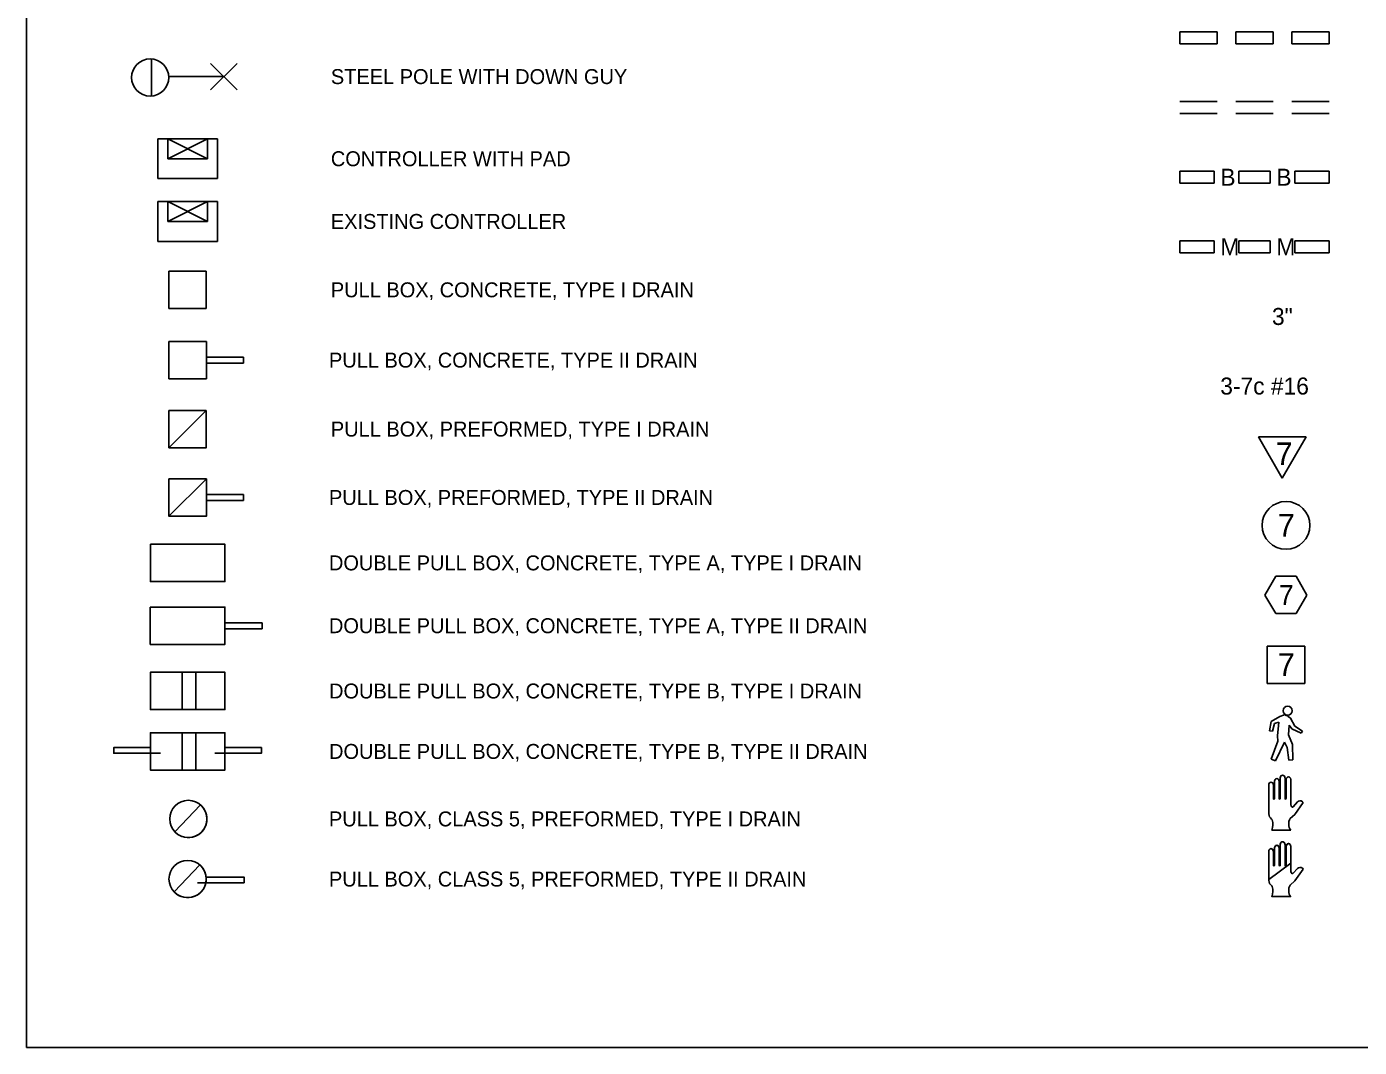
# Model space of a CAD drawing. Extents: x -439.1 to -407.9, y -458.1 to -437.7.
# Drawn here: x -439.11 to -425.73, y -458.05 to -447.8 of the extents above; entities that cross this region are included whole.
import ezdxf

# ---------------------------------------------------------------- set-up
doc = ezdxf.new("R2010")
doc.units = 0
for name, color, linetype in [('Draft_Named_Boundary', 7, 'Continuous'), ('Level 4', 7, 'Continuous'), ('Lighting_Signals-Conduit', 7, 'Continuous'), ('Lighting_Signals-Equipment', 7, 'Continuous')]:
    doc.layers.add(name, color=color, linetype=linetype)

msp = doc.modelspace()

# ---------------------------------------------------------------- linework, layer by layer
at = {"layer": 'Draft_Named_Boundary'}
msp.add_lwpolyline([(-439.109, -458.051), (-407.859, -458.051), (-407.859, -437.676), (-439.109, -437.676)], close=True, dxfattribs=at)
at = {"layer": 'Level 4'}
for p, q in [((-427.533, -447.85), (-427.533, -447.97)), ((-427.533, -447.85), (-427.157, -447.85)), ((-427.157, -447.85), (-427.157, -447.97)), ((-426.97, -447.85), (-426.97, -447.97)), ((-426.97, -447.85), (-426.595, -447.85)), ((-426.595, -447.85), (-426.595, -447.97)), ((-426.408, -447.85), (-426.408, -447.97)), ((-426.408, -447.85), (-426.033, -447.85)), ((-426.033, -447.85), (-426.033, -447.97)), ((-427.533, -447.97), (-427.157, -447.97)), ((-426.97, -447.97), (-426.595, -447.97)), ((-426.408, -447.97), (-426.033, -447.97)), ((-437.856, -448.121), (-437.856, -448.495)), ((-436.997, -448.167), (-437.262, -448.432)), ((-437.262, -448.167), (-436.997, -448.432)), ((-437.682, -448.299), (-437.13, -448.299)), ((-427.533, -448.549), (-427.157, -448.549)), ((-426.97, -448.549), (-426.595, -448.549)), ((-426.408, -448.549), (-426.033, -448.549)), ((-427.533, -448.669), (-427.157, -448.669)), ((-426.97, -448.669), (-426.595, -448.669)), ((-426.408, -448.669), (-426.033, -448.669)), ((-427.533, -449.369), (-427.533, -449.25)), ((-427.533, -449.25), (-427.188, -449.25)), ((-427.188, -449.25), (-427.188, -449.369)), ((-426.94, -449.369), (-426.94, -449.25)), ((-426.94, -449.25), (-426.625, -449.25)), ((-426.625, -449.25), (-426.625, -449.369)), ((-426.378, -449.369), (-426.378, -449.25)), ((-426.378, -449.25), (-426.033, -449.25)), ((-426.033, -449.25), (-426.033, -449.369)), ((-427.188, -449.369), (-427.533, -449.369)), ((-426.625, -449.369), (-426.94, -449.369)), ((-426.033, -449.369), (-426.378, -449.369)), ((-427.533, -450.068), (-427.533, -449.949)), ((-427.533, -449.949), (-427.188, -449.949)), ((-427.188, -450.068), (-427.533, -450.068)), ((-427.188, -449.949), (-427.188, -450.068)), ((-426.94, -450.068), (-426.94, -449.949)), ((-426.94, -449.949), (-426.625, -449.949)), ((-426.625, -450.068), (-426.94, -450.068)), ((-426.625, -449.949), (-426.625, -450.068)), ((-426.378, -450.068), (-426.378, -449.949)), ((-426.378, -449.949), (-426.033, -449.949)), ((-426.033, -450.068), (-426.378, -450.068)), ((-426.033, -449.949), (-426.033, -450.068)), ((-437.306, -450.254), (-437.68, -450.254)), ((-437.68, -450.254), (-437.68, -450.629)), ((-437.306, -450.629), (-437.306, -450.254)), ((-437.68, -450.629), (-437.306, -450.629)), ((-437.305, -450.96), (-437.68, -450.96)), ((-437.68, -450.96), (-437.68, -451.335)), ((-437.305, -451.335), (-437.305, -450.96)), ((-437.305, -451.117), (-436.931, -451.117)), ((-436.931, -451.177), (-436.931, -451.117)), ((-437.305, -451.177), (-436.931, -451.177)), ((-437.68, -451.335), (-437.305, -451.335)), ((-437.68, -451.653), (-437.68, -452.028)), ((-437.68, -451.653), (-437.306, -451.653)), ((-437.306, -451.653), (-437.68, -452.028)), ((-437.306, -451.653), (-437.306, -452.028)), ((-426.264, -451.919), (-426.743, -451.919)), ((-426.743, -451.919), (-426.504, -452.333)), ((-426.504, -452.333), (-426.264, -451.919)), ((-437.68, -452.028), (-437.306, -452.028)), ((-437.68, -452.34), (-437.68, -452.715)), ((-437.68, -452.34), (-437.305, -452.34)), ((-437.68, -452.715), (-437.305, -452.34)), ((-437.305, -452.34), (-437.305, -452.715)), ((-437.305, -452.497), (-436.931, -452.497)), ((-437.305, -452.557), (-436.931, -452.557)), ((-436.931, -452.557), (-436.931, -452.497)), ((-437.68, -452.715), (-437.305, -452.715)), ((-426.677, -453.507), (-426.569, -453.319)), ((-426.569, -453.319), (-426.364, -453.319)), ((-426.256, -453.507), (-426.364, -453.319)), ((-426.677, -453.507), (-426.569, -453.694)), ((-426.256, -453.507), (-426.364, -453.694)), ((-437.118, -453.786), (-436.744, -453.786)), ((-436.744, -453.845), (-436.744, -453.786)), ((-426.569, -453.694), (-426.364, -453.694)), ((-437.118, -453.845), (-436.744, -453.845)), ((-426.654, -454.019), (-426.278, -454.019)), ((-426.654, -454.394), (-426.654, -454.019)), ((-426.278, -454.394), (-426.278, -454.019)), ((-437.867, -454.283), (-437.119, -454.283)), ((-426.654, -454.394), (-426.278, -454.394)), ((-437.119, -454.658), (-437.867, -454.658)), ((-426.614, -454.776), (-426.527, -454.726)), ((-426.527, -454.726), (-426.491, -454.714)), ((-426.491, -454.714), (-426.483, -454.707)), ((-426.491, -454.714), (-426.491, -454.714)), ((-426.483, -454.707), (-426.466, -454.716)), ((-426.466, -454.716), (-426.452, -454.717)), ((-426.452, -454.717), (-426.445, -454.728)), ((-426.445, -454.728), (-426.422, -454.745)), ((-426.422, -454.745), (-426.376, -454.825)), ((-437.867, -454.89), (-437.119, -454.89)), ((-426.632, -454.872), (-426.614, -454.776)), ((-426.602, -454.875), (-426.632, -454.872)), ((-426.58, -454.796), (-426.602, -454.875)), ((-426.537, -454.785), (-426.58, -454.796)), ((-426.551, -454.923), (-426.537, -454.785)), ((-426.433, -454.813), (-426.441, -454.912)), ((-426.406, -454.852), (-426.433, -454.813)), ((-426.315, -454.894), (-426.406, -454.852)), ((-426.376, -454.825), (-426.3, -454.876)), ((-426.3, -454.876), (-426.315, -454.894)), ((-426.614, -455.157), (-426.547, -454.976)), ((-426.481, -454.986), (-426.573, -455.173)), ((-426.547, -454.976), (-426.551, -454.923)), ((-426.453, -455.039), (-426.481, -454.986)), ((-426.441, -454.912), (-426.401, -455.01)), ((-426.401, -455.01), (-426.397, -455.163)), ((-426.573, -455.173), (-426.614, -455.157)), ((-426.438, -455.166), (-426.453, -455.039)), ((-426.397, -455.163), (-426.438, -455.166)), ((-437.119, -455.266), (-437.867, -455.266)), ((-426.639, -455.705), (-426.639, -455.413)), ((-426.592, -455.413), (-426.592, -455.551)), ((-426.581, -455.551), (-426.581, -455.378)), ((-426.534, -455.378), (-426.534, -455.551)), ((-426.523, -455.551), (-426.523, -455.343)), ((-426.476, -455.343), (-426.476, -455.551)), ((-426.465, -455.551), (-426.465, -455.361)), ((-426.418, -455.361), (-426.418, -455.602)), ((-437.365, -455.614), (-437.621, -455.886)), ((-437.365, -455.614), (-437.621, -455.886)), ((-426.413, -455.626), (-426.412, -455.63)), ((-426.393, -455.633), (-426.351, -455.586)), ((-426.301, -455.583), (-426.293, -455.591)), ((-426.418, -455.868), (-426.609, -455.868)), ((-426.639, -456.374), (-426.639, -456.081)), ((-426.592, -456.081), (-426.592, -456.22)), ((-426.581, -456.22), (-426.581, -456.047)), ((-426.534, -456.047), (-426.534, -456.22)), ((-426.523, -456.22), (-426.523, -456.012)), ((-426.476, -456.012), (-426.476, -456.22)), ((-426.465, -456.22), (-426.465, -456.029)), ((-426.418, -456.029), (-426.418, -456.201)), ((-437.372, -456.217), (-437.628, -456.49)), ((-437.372, -456.217), (-437.628, -456.49)), ((-426.639, -456.363), (-426.418, -456.201)), ((-426.418, -456.201), (-426.418, -456.271)), ((-426.413, -456.295), (-426.412, -456.298)), ((-426.393, -456.302), (-426.351, -456.254)), ((-426.301, -456.252), (-426.293, -456.26)), ((-426.418, -456.537), (-426.609, -456.537))]:
    msp.add_line(p, q, dxfattribs=at)
for points in [[(-437.306, -451.653), (-437.68, -452.028), (-437.306, -452.028)], [(-437.305, -452.34), (-437.68, -452.715), (-437.305, -452.715)], [(-437.867, -452.996), (-437.119, -452.996), (-437.119, -453.371), (-437.867, -453.371)], [(-437.868, -453.628), (-437.118, -453.628), (-437.118, -454.003), (-437.868, -454.003)], [(-426.639, -456.363), (-426.639, -456.081), (-426.634, -456.065), (-426.624, -456.057), (-426.61, -456.057), (-426.6, -456.062), (-426.592, -456.081), (-426.592, -456.22), (-426.589, -456.225), (-426.585, -456.225), (-426.582, -456.225), (-426.582, -456.22), (-426.581, -456.22), (-426.581, -456.047), (-426.581, -456.047), (-426.574, -456.03), (-426.558, -456.02), (-426.543, -456.027), (-426.534, -456.047), (-426.534, -456.22), (-426.531, -456.225), (-426.527, -456.225), (-426.524, -456.225), (-426.523, -456.22), (-426.523, -456.012), (-426.523, -456.003), (-426.511, -455.99), (-426.498, -455.986), (-426.483, -455.992), (-426.476, -456.012), (-426.476, -456.22), (-426.476, -456.227), (-426.471, -456.227), (-426.466, -456.227), (-426.466, -456.218), (-426.465, -456.22), (-426.465, -456.029), (-426.459, -456.013), (-426.441, -456.003), (-426.428, -456.01), (-426.418, -456.029), (-426.418, -456.201)]]:
    msp.add_lwpolyline(points, close=True, dxfattribs=at)
for points in [[(-437.549, -454.658), (-437.867, -454.658), (-437.867, -454.283), (-437.549, -454.283)], [(-437.549, -454.283), (-437.549, -454.658)], [(-437.41, -454.658), (-437.41, -454.283)], [(-437.41, -454.283), (-437.119, -454.283), (-437.119, -454.658), (-437.41, -454.658)], [(-437.549, -455.266), (-437.867, -455.266), (-437.867, -454.89), (-437.549, -454.89)], [(-437.549, -454.89), (-437.549, -455.266)], [(-437.41, -455.266), (-437.41, -454.89)], [(-437.41, -454.89), (-437.119, -454.89), (-437.119, -455.266), (-437.41, -455.266)], [(-437.867, -455.04), (-438.234, -455.04), (-438.234, -455.097), (-437.766, -455.097)], [(-437.119, -455.04), (-436.752, -455.04), (-436.752, -455.097), (-437.22, -455.097)], [(-426.293, -455.591), (-426.379, -455.711), (-426.424, -455.753)], [(-437.305, -456.341), (-436.926, -456.341), (-436.926, -456.398), (-437.394, -456.398)], [(-426.293, -456.26), (-426.379, -456.379), (-426.424, -456.421)]]:
    msp.add_lwpolyline(points, dxfattribs=at)
for centre, radius in [((-437.869, -448.308), 0.187), ((-426.466, -452.807), 0.24), ((-426.449, -454.669), 0.0455), ((-437.486, -455.756), 0.187), ((-437.493, -456.36), 0.187)]:
    msp.add_circle(centre, radius, dxfattribs=at)
for centre, start, end in [((-437.486, -455.756), 0, 49.5536), ((-437.486, -455.756), 223.8566, 0), ((-437.493, -456.36), 0, 49.5536), ((-437.493, -456.36), 223.8566, 0)]:
    msp.add_arc(centre, 0.187, start, end, dxfattribs=at)
for centre, major_axis, start_param, end_param in [((-426.616, -455.413), (0, 0.0266), 4.712442, 7.853966), ((-426.558, -455.378), (0, 0.0266), 4.712442, 7.853971), ((-426.5, -455.343), (0, 0.0266), 4.712442, 7.853967), ((-426.441, -455.361), (0, 0.0266), 4.712336, 7.853967), ((-426.587, -455.551), (0, 0.00665), 1.570808, 4.712442), ((-426.529, -455.551), (0, 0.00665), 1.570796, 4.712382), ((-426.471, -455.551), (0, 0.00665), 1.570796, 4.712387), ((-426.372, -455.602), (0, -0.0532), 4.712389, 5.188198), ((-426.401, -455.624), (0, -0.0133), 5.188193, 7.058644), ((-426.325, -455.616), (0, 0.0425), 5.596656, 7.058644), ((-426.574, -455.697), (0, -0.0751), 4.819258, 5.643493), ((-426.627, -455.779), (0, 0.0266), 5.196586, 5.643493), ((-426.705, -455.813), (0, 0.123), 4.24666, 5.108756), ((-426.36, -455.806), (0, 0.0908), 0.939503, 2.323396), ((-426.616, -456.081), (0, 0.0266), 4.712442, 7.853966), ((-426.558, -456.047), (0, 0.0266), 4.712442, 7.853971), ((-426.5, -456.012), (0, 0.0266), 4.712442, 7.853967), ((-426.441, -456.029), (0, 0.0266), 4.712336, 7.853967), ((-426.587, -456.22), (0, 0.00665), 1.570808, 4.712442), ((-426.529, -456.22), (0, 0.00665), 1.570796, 4.712382), ((-426.471, -456.22), (0, 0.00665), 1.570796, 4.712387), ((-426.372, -456.271), (0, -0.0532), 4.712389, 5.188198), ((-426.401, -456.292), (0, -0.0133), 5.188193, 7.058644), ((-426.325, -456.285), (0, 0.0425), 5.596656, 7.058644), ((-426.574, -456.366), (0, -0.0751), 4.819258, 5.643493), ((-426.627, -456.447), (0, 0.0266), 5.196586, 5.643493), ((-426.705, -456.482), (0, 0.123), 4.24666, 5.108756), ((-426.36, -456.475), (0, 0.0908), 0.939503, 2.323396)]:
    msp.add_ellipse(centre, major_axis=major_axis, ratio=0.872945, start_param=start_param, end_param=end_param, dxfattribs=at)
at = {"layer": 'Lighting_Signals-Conduit'}
for p, q in [((-437.693, -449.754), (-437.693, -449.554)), ((-437.693, -449.554), (-437.293, -449.754)), ((-437.293, -449.554), (-437.693, -449.754)), ((-437.693, -449.754), (-437.293, -449.554)), ((-437.293, -449.754), (-437.693, -449.554)), ((-437.693, -449.554), (-437.693, -449.754)), ((-437.293, -449.554), (-437.293, -449.754))]:
    msp.add_line(p, q, dxfattribs=at)
at = {"layer": 'Lighting_Signals-Equipment'}
for p, q in [((-437.193, -448.924), (-437.793, -448.924)), ((-437.793, -448.924), (-437.793, -449.324)), ((-437.693, -449.124), (-437.693, -448.924)), ((-437.693, -448.924), (-437.293, -449.124)), ((-437.293, -448.924), (-437.693, -449.124)), ((-437.693, -448.924), (-437.293, -449.124)), ((-437.293, -448.924), (-437.693, -449.124)), ((-437.693, -449.124), (-437.693, -448.924)), ((-437.693, -448.924), (-437.293, -449.124)), ((-437.293, -448.924), (-437.693, -449.124)), ((-437.693, -449.124), (-437.693, -448.924)), ((-437.293, -449.124), (-437.693, -448.924)), ((-437.693, -449.124), (-437.293, -448.924)), ((-437.293, -448.924), (-437.293, -449.124)), ((-437.193, -449.324), (-437.193, -448.924)), ((-437.293, -449.124), (-437.693, -449.124)), ((-437.793, -449.324), (-437.193, -449.324)), ((-437.193, -449.554), (-437.793, -449.554)), ((-437.793, -449.554), (-437.793, -449.954)), ((-437.193, -449.954), (-437.193, -449.554)), ((-437.293, -449.754), (-437.693, -449.754)), ((-437.793, -449.954), (-437.193, -449.954))]:
    msp.add_line(p, q, dxfattribs=at)

# ---------------------------------------------------------------- texts
at = {"layer": 'Level 4'}
for s, height, p in [('STEEL POLE WITH DOWN GUY', 0.15, (-436.055, -448.374)), ('CONTROLLER WITH PAD', 0.15, (-436.055, -449.199)), ('B', 0.171, (-427.125, -449.395)), ('B', 0.171, (-426.563, -449.395)), ('EXISTING CONTROLLER', 0.15, (-436.055, -449.829)), ('M', 0.171, (-427.125, -450.094)), ('M', 0.171, (-426.563, -450.094)), ('PULL BOX, CONCRETE, TYPE I DRAIN', 0.15, (-436.055, -450.516)), ('3"', 0.171, (-426.607, -450.794)), ('PULL BOX, CONCRETE, TYPE II DRAIN', 0.15, (-436.074, -451.222)), ('3-7c #16', 0.171, (-427.126, -451.493)), ('PULL BOX, PREFORMED, TYPE I DRAIN', 0.15, (-436.055, -451.915)), ('7', 0.228, (-426.57, -452.202)), ('PULL BOX, PREFORMED, TYPE II DRAIN', 0.15, (-436.074, -452.602)), ('7', 0.228, (-426.548, -452.921)), ('DOUBLE PULL BOX, CONCRETE, TYPE A, TYPE I DRAIN', 0.15, (-436.074, -453.259)), ('7', 0.199, (-426.537, -453.606)), ('DOUBLE PULL BOX, CONCRETE, TYPE A, TYPE II DRAIN', 0.15, (-436.074, -453.89)), ('7', 0.228, (-426.548, -454.32)), ('DOUBLE PULL BOX, CONCRETE, TYPE B, TYPE I DRAIN', 0.15, (-436.073, -454.546)), ('DOUBLE PULL BOX, CONCRETE, TYPE B, TYPE II DRAIN', 0.15, (-436.073, -455.153)), ('PULL BOX, CLASS 5, PREFORMED, TYPE I DRAIN', 0.15, (-436.074, -455.831)), ('PULL BOX, CLASS 5, PREFORMED, TYPE II DRAIN', 0.15, (-436.074, -456.435))]:
    msp.add_text(s, height=height, dxfattribs=at).set_placement(p)

doc.saveas('drawing.dxf')
